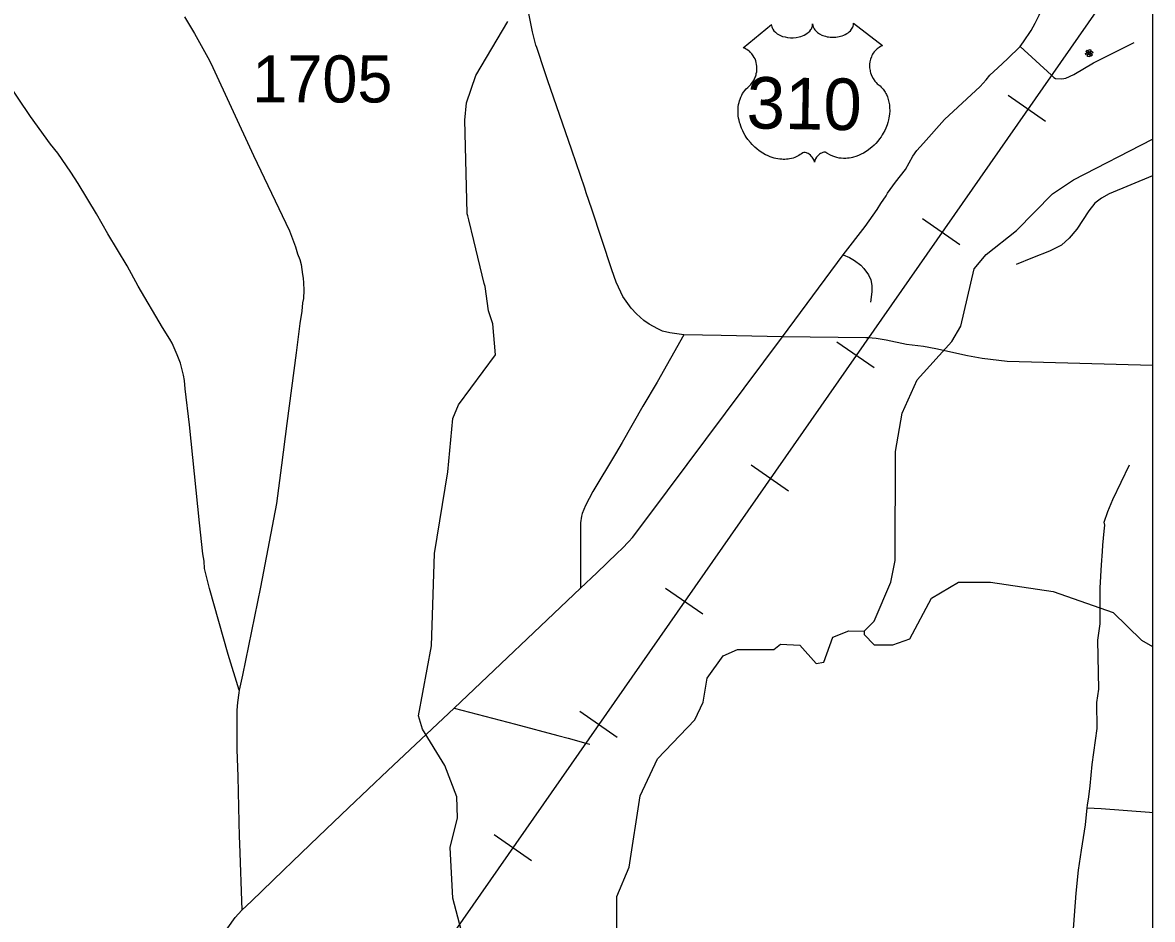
# Model space of a CAD drawing. Extents: x 0 to 2021, y 0 to 1321.
# Drawn here: x 541.9 to 654.8, y 969 to 1058.6 of the extents above; entities that cross this region are included whole.
import ezdxf

# ---------------------------------------------------------------- set-up
doc = ezdxf.new("R2010")
doc.units = 0
for name, color, linetype in [('Default', 7, 'Continuous'), ('Exist Hydro Stream or Body of Water', 7, 'Continuous'), ('Miscellaneous Lines', 7, 'Continuous'), ('Old_Level_26', 7, 'Continuous'), ('Scratch_Level_0', 7, 'Continuous'), ('Sheet Title CELL', 7, 'Continuous'), ('Text', 7, 'Continuous')]:
    doc.layers.add(name, color=color, linetype=linetype)

msp = doc.modelspace()

# ---------------------------------------------------------------- linework, layer by layer
at = {"layer": 'Default'}
for p, q in [((613.89, 1056.12), (616.72, 1058.45)), ((616.73, 1058.33), (616.72, 1058.45)), ((616.73, 1058.33), (616.76, 1058.19)), ((616.76, 1058.19), (616.78, 1058.12)), ((616.78, 1058.12), (616.85, 1057.98)), ((616.85, 1057.98), (616.96, 1057.81)), ((616.96, 1057.81), (617.12, 1057.66)), ((620.38, 1057.64), (620.53, 1057.78)), ((620.53, 1057.78), (620.65, 1057.94)), ((620.65, 1057.94), (620.7, 1058.02)), ((620.7, 1058.02), (620.74, 1058.1)), ((620.74, 1058.1), (620.8, 1058.28)), ((620.8, 1058.28), (620.81, 1058.35)), ((620.81, 1058.35), (620.82, 1058.51)), ((620.82, 1058.51), (620.83, 1058.38)), ((620.83, 1058.38), (620.85, 1058.3)), ((620.85, 1058.3), (620.87, 1058.22)), ((620.87, 1058.22), (620.91, 1058.13)), ((620.91, 1058.13), (620.97, 1058.01)), ((620.97, 1058.01), (621.04, 1057.91)), ((621.04, 1057.91), (621.17, 1057.76)), ((621.17, 1057.76), (621.25, 1057.69)), ((624.48, 1057.7), (624.61, 1057.82)), ((624.61, 1057.82), (624.72, 1057.96)), ((624.72, 1057.96), (624.79, 1058.06)), ((624.79, 1058.06), (624.84, 1058.17)), ((624.84, 1058.17), (624.88, 1058.27)), ((624.88, 1058.27), (624.91, 1058.39)), ((624.91, 1058.39), (624.92, 1058.49)), ((624.92, 1058.58), (627.82, 1056.33)), ((624.92, 1058.49), (624.92, 1058.58)), ((617.12, 1057.66), (617.29, 1057.52)), ((617.29, 1057.52), (617.41, 1057.44)), ((617.41, 1057.44), (617.6, 1057.34)), ((617.6, 1057.34), (617.83, 1057.25)), ((617.83, 1057.25), (618.07, 1057.19)), ((618.07, 1057.19), (618.33, 1057.14)), ((618.33, 1057.14), (618.6, 1057.11)), ((618.6, 1057.11), (618.88, 1057.11)), ((618.88, 1057.11), (619.17, 1057.14)), ((619.17, 1057.14), (619.49, 1057.2)), ((619.49, 1057.2), (619.64, 1057.25)), ((619.64, 1057.25), (619.81, 1057.31)), ((619.81, 1057.31), (619.97, 1057.37)), ((619.97, 1057.37), (620.14, 1057.47)), ((620.14, 1057.47), (620.27, 1057.56)), ((620.27, 1057.56), (620.38, 1057.64)), ((621.25, 1057.69), (621.32, 1057.63)), ((621.32, 1057.63), (621.52, 1057.5)), ((621.52, 1057.5), (621.75, 1057.38)), ((621.75, 1057.38), (621.86, 1057.34)), ((621.86, 1057.34), (621.98, 1057.3)), ((621.98, 1057.3), (622.12, 1057.26)), ((622.12, 1057.26), (622.27, 1057.22)), ((622.27, 1057.22), (622.42, 1057.2)), ((622.42, 1057.2), (622.58, 1057.18)), ((622.58, 1057.18), (622.73, 1057.17)), ((622.73, 1057.17), (622.86, 1057.17)), ((622.86, 1057.17), (623.02, 1057.17)), ((623.02, 1057.17), (623.16, 1057.18)), ((623.16, 1057.18), (623.31, 1057.2)), ((623.31, 1057.2), (623.47, 1057.23)), ((623.47, 1057.23), (623.6, 1057.26)), ((623.6, 1057.26), (623.77, 1057.31)), ((623.77, 1057.31), (623.93, 1057.37)), ((623.93, 1057.37), (624.06, 1057.43)), ((624.06, 1057.43), (624.24, 1057.53)), ((624.24, 1057.53), (624.38, 1057.62)), ((624.38, 1057.62), (624.48, 1057.7)), ((613.98, 1056.09), (613.89, 1056.12)), ((614.12, 1056.02), (613.98, 1056.09)), ((614.26, 1055.93), (614.12, 1056.02)), ((614.38, 1055.85), (614.26, 1055.93)), ((614.51, 1055.76), (614.38, 1055.85)), ((614.63, 1055.63), (614.51, 1055.76)), ((614.76, 1055.49), (614.63, 1055.63)), ((614.89, 1055.32), (614.76, 1055.49)), ((626.89, 1055.57), (626.82, 1055.46)), ((626.97, 1055.69), (626.89, 1055.57)), ((627.04, 1055.77), (626.97, 1055.69)), ((627.12, 1055.85), (627.04, 1055.77)), ((627.2, 1055.94), (627.12, 1055.85)), ((627.28, 1056.01), (627.2, 1055.94)), ((627.48, 1056.15), (627.28, 1056.01)), ((627.6, 1056.23), (627.48, 1056.15)), ((627.76, 1056.31), (627.6, 1056.23)), ((627.82, 1056.33), (627.76, 1056.31)), ((615, 1055.13), (614.89, 1055.32)), ((615.07, 1055), (615, 1055.13)), ((615.14, 1054.81), (615.07, 1055)), ((615.19, 1054.64), (615.14, 1054.81)), ((615.23, 1054.45), (615.19, 1054.64)), ((615.25, 1054.26), (615.23, 1054.45)), ((626.52, 1054.46), (626.51, 1054.34)), ((626.55, 1054.71), (626.52, 1054.46)), ((626.57, 1054.84), (626.55, 1054.71)), ((626.61, 1054.98), (626.57, 1054.84)), ((626.7, 1055.22), (626.61, 1054.98)), ((626.75, 1055.33), (626.7, 1055.22)), ((626.82, 1055.46), (626.75, 1055.33)), ((615.11, 1053.21), (615.17, 1053.41)), ((615.17, 1053.41), (615.2, 1053.54)), ((615.2, 1053.54), (615.24, 1053.72)), ((615.24, 1053.72), (615.25, 1053.88)), ((615.26, 1054.09), (615.25, 1054.26)), ((615.25, 1053.88), (615.26, 1054.09)), ((626.51, 1054.34), (626.51, 1054.22)), ((626.51, 1054.22), (626.52, 1054.09)), ((626.52, 1054.09), (626.53, 1053.97)), ((626.53, 1053.97), (626.56, 1053.84)), ((626.56, 1053.84), (626.58, 1053.73)), ((626.58, 1053.73), (626.62, 1053.59)), ((626.62, 1053.59), (626.67, 1053.43)), ((626.67, 1053.43), (626.74, 1053.28)), ((626.74, 1053.28), (626.87, 1053.03)), ((614.19, 1052.01), (614.34, 1052.15)), ((614.34, 1052.15), (614.48, 1052.27)), ((614.48, 1052.27), (614.64, 1052.44)), ((614.64, 1052.44), (614.73, 1052.53)), ((614.73, 1052.53), (614.83, 1052.67)), ((614.83, 1052.67), (614.91, 1052.8)), ((614.91, 1052.8), (614.97, 1052.92)), ((614.97, 1052.92), (615.06, 1053.09)), ((615.06, 1053.09), (615.11, 1053.21)), ((626.87, 1053.03), (627.04, 1052.78)), ((627.04, 1052.78), (627.16, 1052.64)), ((627.16, 1052.64), (627.28, 1052.52)), ((627.28, 1052.52), (627.46, 1052.37)), ((627.46, 1052.37), (627.56, 1052.29)), ((627.56, 1052.29), (627.67, 1052.18)), ((627.67, 1052.18), (627.86, 1051.98)), ((613.51, 1050.8), (613.57, 1050.98)), ((613.57, 1050.98), (613.65, 1051.18)), ((613.65, 1051.18), (613.74, 1051.37)), ((613.74, 1051.37), (613.83, 1051.53)), ((613.83, 1051.53), (613.94, 1051.7)), ((613.94, 1051.7), (614.05, 1051.85)), ((614.05, 1051.85), (614.19, 1052.01)), ((627.86, 1051.98), (627.93, 1051.88)), ((627.93, 1051.88), (628, 1051.77)), ((628, 1051.77), (628.07, 1051.66)), ((628.07, 1051.66), (628.14, 1051.54)), ((628.14, 1051.54), (628.2, 1051.43)), ((628.2, 1051.43), (628.3, 1051.19)), ((628.3, 1051.19), (628.38, 1050.95)), ((613.37, 1049.98), (613.39, 1050.21)), ((613.37, 1049.79), (613.37, 1049.98)), ((613.39, 1050.21), (613.43, 1050.45)), ((613.43, 1050.45), (613.47, 1050.65)), ((613.47, 1050.65), (613.51, 1050.8)), ((628.38, 1050.95), (628.42, 1050.82)), ((628.42, 1050.82), (628.47, 1050.54)), ((628.47, 1050.54), (628.5, 1050.41)), ((628.5, 1050.41), (628.52, 1050.13)), ((628.52, 1050.13), (628.53, 1049.8)), ((613.38, 1049.56), (613.37, 1049.79)), ((613.4, 1049.3), (613.38, 1049.56)), ((613.43, 1049.06), (613.4, 1049.3)), ((613.47, 1048.89), (613.43, 1049.06)), ((613.53, 1048.65), (613.47, 1048.89)), ((628.41, 1048.9), (628.34, 1048.64)), ((628.45, 1049.12), (628.41, 1048.9)), ((628.51, 1049.48), (628.45, 1049.12)), ((628.53, 1049.8), (628.51, 1049.48)), ((613.57, 1048.51), (613.53, 1048.65)), ((613.64, 1048.29), (613.57, 1048.51)), ((613.73, 1048.06), (613.64, 1048.29)), ((613.84, 1047.8), (613.73, 1048.06)), ((613.93, 1047.63), (613.84, 1047.8)), ((614.09, 1047.35), (613.93, 1047.63)), ((628.03, 1047.85), (627.88, 1047.57)), ((628.14, 1048.09), (628.03, 1047.85)), ((628.27, 1048.42), (628.14, 1048.09)), ((628.34, 1048.64), (628.27, 1048.42)), ((614.19, 1047.18), (614.09, 1047.35)), ((614.36, 1046.95), (614.19, 1047.18)), ((614.61, 1046.63), (614.36, 1046.95)), ((614.78, 1046.45), (614.61, 1046.63)), ((627.13, 1046.55), (626.97, 1046.38)), ((627.34, 1046.79), (627.13, 1046.55)), ((627.51, 1047.01), (627.34, 1046.79)), ((627.66, 1047.22), (627.51, 1047.01)), ((627.78, 1047.4), (627.66, 1047.22)), ((627.88, 1047.57), (627.78, 1047.4)), ((615.05, 1046.18), (614.78, 1046.45)), ((615.24, 1046.01), (615.05, 1046.18)), ((615.5, 1045.81), (615.24, 1046.01)), ((615.84, 1045.58), (615.5, 1045.81)), ((616.12, 1045.42), (615.84, 1045.58)), ((616.31, 1045.33), (616.12, 1045.42)), ((616.57, 1045.22), (616.31, 1045.33)), ((619.46, 1045.35), (619.3, 1045.26)), ((619.59, 1045.43), (619.46, 1045.35)), ((619.71, 1045.52), (619.59, 1045.43)), ((619.84, 1045.61), (619.71, 1045.52)), ((619.94, 1045.64), (619.84, 1045.61)), ((620.01, 1045.64), (619.94, 1045.64)), ((620.09, 1045.63), (620.01, 1045.64)), ((620.2, 1045.61), (620.09, 1045.63)), ((620.28, 1045.58), (620.2, 1045.61)), ((620.37, 1045.53), (620.28, 1045.58)), ((620.49, 1045.47), (620.37, 1045.53)), ((620.6, 1045.38), (620.49, 1045.47)), ((620.69, 1045.29), (620.6, 1045.38)), ((621.43, 1045.4), (621.34, 1045.31)), ((621.51, 1045.47), (621.43, 1045.4)), ((621.62, 1045.54), (621.51, 1045.47)), ((621.7, 1045.58), (621.62, 1045.54)), ((621.83, 1045.64), (621.7, 1045.58)), ((621.96, 1045.67), (621.83, 1045.64)), ((622.1, 1045.66), (621.96, 1045.67)), ((622.15, 1045.65), (622.1, 1045.66)), ((622.26, 1045.59), (622.15, 1045.65)), ((622.61, 1045.38), (622.26, 1045.59)), ((622.83, 1045.28), (622.61, 1045.38)), ((625.49, 1045.37), (625.23, 1045.27)), ((625.68, 1045.46), (625.49, 1045.37)), ((625.9, 1045.58), (625.68, 1045.46)), ((626.16, 1045.73), (625.9, 1045.58)), ((626.42, 1045.91), (626.16, 1045.73)), ((626.61, 1046.06), (626.42, 1045.91)), ((626.74, 1046.17), (626.61, 1046.06)), ((626.97, 1046.38), (626.74, 1046.17)), ((616.78, 1045.15), (616.57, 1045.22)), ((616.97, 1045.09), (616.78, 1045.15)), ((617.16, 1045.04), (616.97, 1045.09)), ((617.34, 1045), (617.16, 1045.04)), ((617.56, 1044.97), (617.34, 1045)), ((617.74, 1044.96), (617.56, 1044.97)), ((617.89, 1044.95), (617.74, 1044.96)), ((618.05, 1044.95), (617.89, 1044.95)), ((618.2, 1044.96), (618.05, 1044.95)), ((618.37, 1044.98), (618.2, 1044.96)), ((618.53, 1045), (618.37, 1044.98)), ((618.71, 1045.04), (618.53, 1045)), ((618.89, 1045.09), (618.71, 1045.04)), ((619.05, 1045.15), (618.89, 1045.09)), ((619.19, 1045.2), (619.05, 1045.15)), ((619.3, 1045.26), (619.19, 1045.2)), ((620.79, 1045.18), (620.69, 1045.29)), ((620.86, 1045.09), (620.79, 1045.18)), ((620.92, 1044.99), (620.86, 1045.09)), ((620.97, 1044.87), (620.92, 1044.99)), ((621.02, 1044.69), (620.97, 1044.87)), ((621.05, 1044.84), (621.02, 1044.69)), ((621.09, 1044.93), (621.05, 1044.84)), ((621.12, 1045.01), (621.09, 1044.93)), ((621.22, 1045.17), (621.12, 1045.01)), ((621.27, 1045.23), (621.22, 1045.17)), ((621.34, 1045.31), (621.27, 1045.23)), ((623.03, 1045.2), (622.83, 1045.28)), ((623.26, 1045.13), (623.03, 1045.2)), ((623.48, 1045.09), (623.26, 1045.13)), ((623.69, 1045.06), (623.48, 1045.09)), ((623.92, 1045.05), (623.69, 1045.06)), ((624.14, 1045.05), (623.92, 1045.05)), ((624.3, 1045.07), (624.14, 1045.05)), ((624.48, 1045.08), (624.3, 1045.07)), ((624.66, 1045.11), (624.48, 1045.08)), ((624.81, 1045.15), (624.66, 1045.11)), ((625.23, 1045.27), (624.81, 1045.15)), ((617.81, 1027.2), (623.87, 1035.42)), ((585.02, 990.08), (597.63, 1002.08))]:
    msp.add_line(p, q, dxfattribs=at)
for points in [[(641.56, 1056.23), (641.9, 1056.69), (642.67, 1057.83), (643.07, 1058.58), (643.46, 1059.36), (644.69, 1062.27), (645.78, 1065.17), (646.25, 1066.27), (647, 1068.2), (647.26, 1068.76), (647.42, 1069.06), (647.66, 1069.61)], [(644.69, 1053.37), (644.93, 1053.15), (645.09, 1053.04), (645.74, 1052.99), (646.14, 1053.06), (646.93, 1053.45), (648.88, 1054.6), (652.96, 1056.64)], [(631.89, 1046.56), (634.01, 1048.93), (637.55, 1052.24), (638.16, 1052.9), (638.54, 1053.37), (639.34, 1054.12), (640.28, 1055.02), (641.56, 1056.23)], [(641.56, 1056.23), (644.69, 1053.37)], [(623.87, 1035.42), (626.08, 1038.26), (627.27, 1039.95), (627.63, 1040.55), (628.17, 1041.31), (628.3, 1041.57), (629.1, 1042.66), (630.09, 1043.93), (630.84, 1045.29), (631.24, 1045.83), (631.89, 1046.56)], [(654.77, 1043.31), (650.47, 1041.52), (649.68, 1041.07), (649.03, 1040.57), (648.42, 1039.82), (647.21, 1037.98), (646.46, 1037.08), (645.68, 1036.38), (644.5, 1035.79), (642.8, 1035.12), (641.16, 1034.44)], [(597.63, 1002.08), (599.26, 1003.61), (601.29, 1005.6), (601.81, 1006.05), (602.47, 1006.75), (602.84, 1007.16), (604.46, 1009.32), (617.81, 1027.2)], [(563.8, 969.91), (564.77, 970.8), (567.97, 973.9), (568.84, 974.75), (571.46, 977.25), (574.46, 980.13), (578.39, 983.86), (585.02, 990.08)], [(598.17, 986.61), (598.57, 986.5)], [(575.29, 953.78), (571.9, 956.15), (568.86, 958.28), (565.67, 960.51), (562.87, 962.39), (559.85, 964.5), (561.82, 967.32), (563.13, 969.18), (563.8, 969.91)]]:
    msp.add_lwpolyline(points, dxfattribs=at)
for points in [[(648.15, 1055.36), (648.09, 1055.54), (648.77, 1055.77), (648.83, 1055.59)], [(648.13, 1055.73), (648.26, 1055.87), (648.79, 1055.4), (648.67, 1055.26)], [(648.44, 1055.94), (648.63, 1055.9), (648.48, 1055.2), (648.3, 1055.24)]]:
    msp.add_lwpolyline(points, close=True, dxfattribs=at)
at = {"layer": 'Exist Hydro Stream or Body of Water'}
for points in [[(586.09, 1048.86), (586.25, 1050.62), (587.17, 1053.33), (590.36, 1058.75)], [(586.31, 1039.52), (586.3, 1039.58), (586.09, 1048.86)], [(625.97, 997.78), (626.98, 998.79), (628.65, 1002.68), (629.07, 1004.86), (629.1, 1015.76), (629.76, 1019.57), (631.27, 1022.93), (634.72, 1026.75), (635.64, 1028.29), (636.97, 1034.02), (638.15, 1035.46), (641.18, 1037.85), (644.79, 1041.5), (646.9, 1042.92), (654.77, 1046.99)], [(586.36, 1039.31), (586.31, 1039.52)], [(586.46, 1038.92), (586.36, 1039.31)], [(586.97, 1036.85), (586.46, 1038.92)], [(588.02, 1032.55), (586.97, 1036.85)], [(586.24, 965.89), (584.88, 971.1), (584.6, 976.16), (585.35, 979.14), (585.26, 981.23), (584.06, 984.35), (581.86, 987.98), (581.43, 989.32), (582.75, 996.34), (583.05, 1005.54), (584.37, 1013.73), (584.86, 1019.04), (585.45, 1020.42), (589.14, 1025.4), (588.87, 1028.53), (588.44, 1029.8), (588.1, 1032.23), (588.02, 1032.55)], [(625.97, 997.78), (625.97, 997.45), (626.98, 996.43), (628.84, 996.42), (630.53, 997.02), (632.71, 1001.1), (635.4, 1002.7), (638.61, 1002.7), (644.86, 1001.74), (650.86, 999.66), (653.67, 996.88), (654.77, 996.26)], [(601.26, 968.04), (601.25, 971.26), (602.5, 974.19), (603.58, 981.32), (605.34, 985.04), (609.04, 988.92), (609.88, 990.7), (610.28, 993.08), (611.87, 995.34), (613.31, 995.95), (616.94, 995.97), (617.62, 996.49), (619.56, 996.38), (621.17, 994.55), (621.93, 994.7), (622.85, 997.18), (624.44, 997.84), (625.97, 997.78)]]:
    msp.add_lwpolyline(points, dxfattribs=at)
at = {"layer": 'Miscellaneous Lines'}
for p, q in [((654.77, 1067.84), (571.32, 948.09)), ((640.37, 1051.37), (644.09, 1048.78)), ((631.81, 1039.05), (635.53, 1036.46)), ((623.25, 1026.73), (626.97, 1024.15)), ((614.69, 1014.41), (618.41, 1011.83)), ((606.13, 1002.1), (609.85, 999.51)), ((597.57, 989.78), (601.29, 987.19)), ((589.01, 977.46), (592.73, 974.88))]:
    msp.add_line(p, q, dxfattribs=at)
at = {"layer": 'Old_Level_26'}
for points in [[(593.26, 1056.14), (593.16, 1056.38), (593.05, 1056.89), (592.82, 1057.71), (592.44, 1059.7), (592.32, 1061.08), (592.27, 1062.62), (592.34, 1066.73), (592.31, 1067.4), (592.22, 1067.99), (591.99, 1069.37), (591.41, 1071.64), (590.32, 1076.08), (589.97, 1077.42), (589.78, 1078.36), (589.68, 1079.17), (589.63, 1079.92), (589.73, 1080.95), (589.85, 1081.84), (590.04, 1082.87), (590.36, 1084.04), (591.14, 1087.16), (591.55, 1088.66)], [(558.08, 1059.19), (559.06, 1057.53), (560.41, 1055.15), (560.7, 1054.56), (564.96, 1045.33), (568.54, 1037.8), (569.15, 1036.21), (569.36, 1035.51), (569.58, 1034.96), (569.71, 1034.45), (569.8, 1033.94), (569.85, 1033.46), (569.92, 1033.07), (569.95, 1032.6), (569.98, 1031.87), (569.94, 1031.06), (569.87, 1030.6), (569.79, 1029.77), (569.59, 1028.56), (569.22, 1025.61), (568.3, 1018.54), (567.77, 1014.37), (567.25, 1010.55), (565.66, 1002.2), (563.87, 993.38), (563.54, 991.88)], [(598.05, 1042.09), (596.77, 1045.87), (594.32, 1052.91), (594.12, 1053.49), (593.99, 1053.91), (593.33, 1055.95), (593.26, 1056.14)], [(563.54, 991.88), (562.42, 995.47), (560.57, 1002.06), (560.06, 1004.05), (560.02, 1004.78), (559.91, 1005.52), (559.57, 1008.62), (558.56, 1018.43), (558.14, 1022.03), (558.08, 1022.84), (557.97, 1023.39), (557.65, 1024.59), (557.32, 1025.41), (556.82, 1026.57), (556.6, 1026.98), (555.88, 1028.16), (553.45, 1032.28), (552.32, 1034.3), (550.4, 1037.51), (549.26, 1039.5), (547.44, 1042.55), (546.72, 1043.68), (545.42, 1045.57), (544.68, 1046.46), (542.68, 1049.24), (540.22, 1052.91)], [(607.94, 1027.4), (606.55, 1027.62), (605.84, 1027.79), (605.36, 1028), (604.5, 1028.47), (603.96, 1028.84), (603.22, 1029.51), (602.69, 1030.09), (601.86, 1031.26), (601.65, 1031.67), (601.2, 1032.69), (600.77, 1033.92), (598.76, 1039.99), (598.21, 1041.62), (598.05, 1042.09)], [(623.87, 1035.42), (624.52, 1035.13), (625, 1034.83), (625.63, 1034.38), (625.95, 1034.06), (626.4, 1033.41), (626.64, 1032.92), (626.73, 1032.33), (626.73, 1031.7), (626.61, 1030.67)], [(607.94, 1027.4), (605.29, 1022.68), (603.86, 1020.27), (601.79, 1016.65), (601.13, 1015.51), (598.86, 1011.74), (598.13, 1010.36), (597.81, 1009.56), (597.74, 1009.3), (597.64, 1008.61), (597.63, 1002.08)], [(617.81, 1027.2), (611.69, 1027.35), (607.94, 1027.4)], [(626.38, 1027.1), (626.13, 1027.11), (617.81, 1027.2)], [(654.77, 1024.34), (640.27, 1024.75), (637.78, 1025.05), (636.29, 1025.32), (633.12, 1026.01), (631.89, 1026.24), (630.19, 1026.46), (628.17, 1026.89), (627.19, 1027.05), (626.38, 1027.1)], [(649.78, 1005.76), (649.83, 1006.39), (649.96, 1007.8), (650.01, 1008.38), (649.95, 1008.69), (650.31, 1009.75), (650.81, 1010.96), (652.5, 1014.41)], [(648.25, 980.12), (648.28, 980.41), (648.42, 981.22), (648.55, 982.32), (648.77, 984.46), (649.27, 988.06), (649.23, 990.66), (649.41, 991.98), (649.32, 996.9), (649.55, 998.54), (649.55, 1002.11), (649.69, 1004.43), (649.78, 1005.76)], [(563.54, 991.88), (563.49, 991.64), (563.35, 990.67), (563.28, 989.88), (563.29, 988.75), (563.3, 985.95), (563.38, 983.27), (563.46, 980.21), (563.54, 977.27), (563.55, 976.56), (563.8, 969.91)], [(585.02, 990.08), (591.13, 988.5), (595.37, 987.36), (596.4, 987.08), (598.17, 986.61)], [(646.69, 962.7), (646.83, 967.13), (647.15, 971.59), (647.4, 973.91), (647.69, 975.89), (648.1, 978.43), (648.25, 980.12)], [(648.25, 980.12), (649.66, 980.05), (654.48, 979.68), (654.77, 979.66)]]:
    msp.add_lwpolyline(points, dxfattribs=at)
at = {"layer": 'Scratch_Level_0'}
msp.add_lwpolyline([(318.71, 1236.23), (654.77, 1236.23), (654.77, 948.09), (318.71, 948.09)], close=True, dxfattribs=at)
at = {"layer": 'Sheet Title CELL'}
msp.add_line((654.77, 1236.23), (654.77, 888.06), dxfattribs=at)

# ---------------------------------------------------------------- texts
at = {"layer": 'Default'}
for s, height, rotation, p in [('1705', 4.705, 360, (564.84, 1050.64)), ('310', 5.153, 358.9625, (614.2, 1048.06))]:
    msp.add_text(s, height=height, rotation=rotation, dxfattribs=at).set_placement(p)
at = {"layer": 'Text'}
msp.add_text('1705', height=4.705, rotation=360, dxfattribs=at).set_placement((564.84, 1050.64))

doc.saveas('drawing.dxf')
